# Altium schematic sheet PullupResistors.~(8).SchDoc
size A4
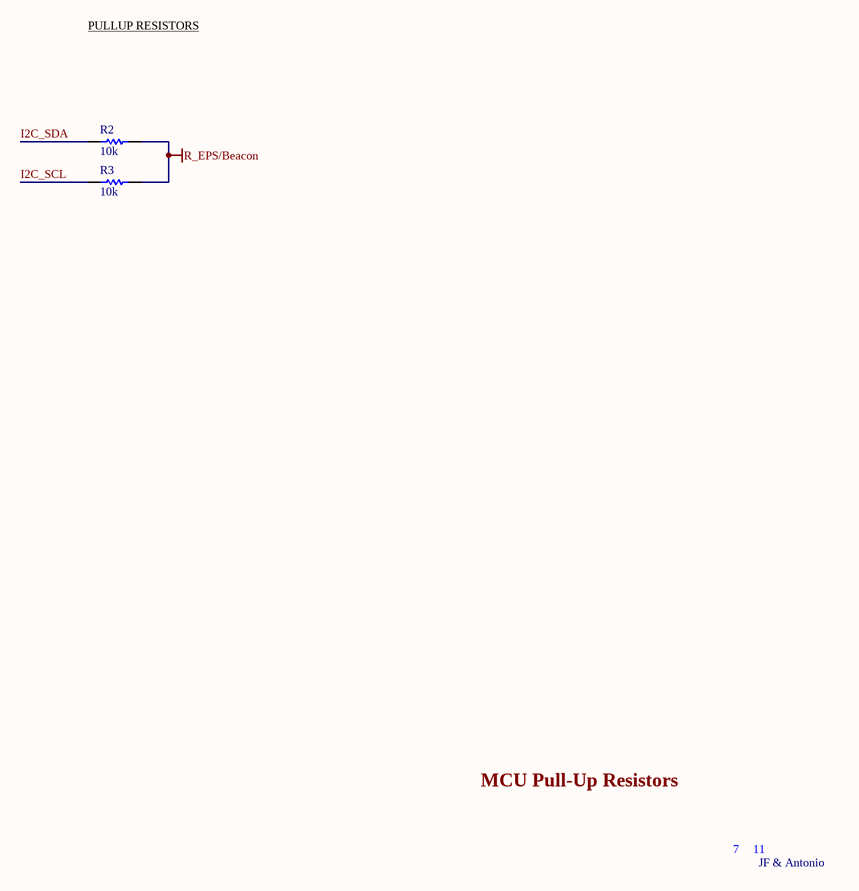
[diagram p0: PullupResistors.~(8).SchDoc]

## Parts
R2  10k  [R10k]
R3  10k  [R10k]

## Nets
R_EPS/Beacon: R2.2 R3.2
I2C_SCL: R3.1
I2C_SDA: R2.1

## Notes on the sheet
- PULLUP RESISTORS
- MCU Pull-Up Resistors
- 7
- 11
- JF & Antonio

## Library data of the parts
R2 R3 = Res1: Resistor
